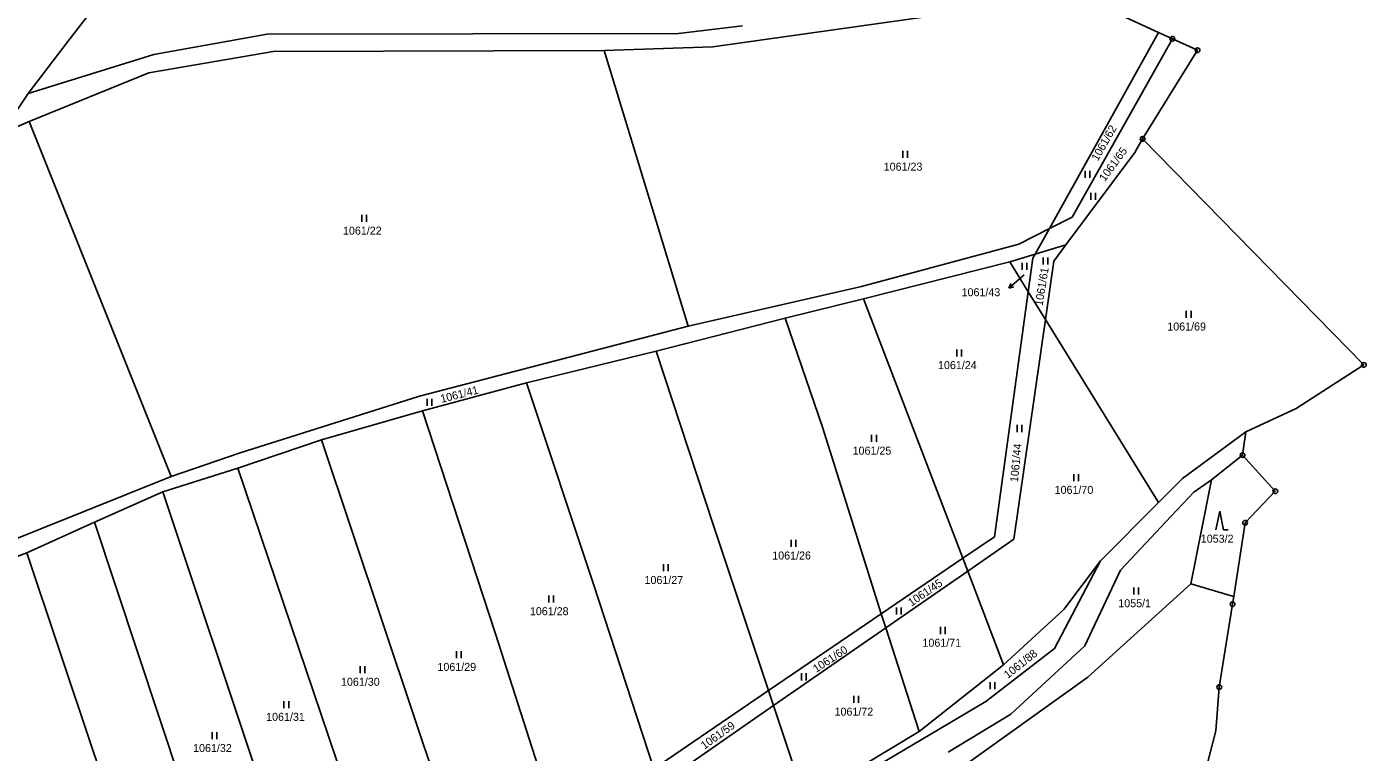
# Model space of a CAD drawing. Extents: x -794142 to -791199, y -1109267 to -1105626.
# Drawn here: x -791483.8 to -791199.2, y -1108972 to -1108817.8 of the extents above; entities that cross this region are included whole.
import ezdxf

# ---------------------------------------------------------------- set-up
doc = ezdxf.new("R2010")
doc.units = 0
for name, color, linetype in [('Komunikace', 7, 'Continuous'), ('Vrstva 1', 7, 'Continuous'), ('Vrstva 14', 7, 'Continuous'), ('Vrstva 16', 7, 'Continuous'), ('Vrstva 23', 7, 'Continuous'), ('Vrstva 28', 7, 'Continuous'), ('Vrstva 4', 7, 'Continuous')]:
    doc.layers.add(name, color=color, linetype=linetype)

msp = doc.modelspace()

# ---------------------------------------------------------------- linework, layer by layer
at = {"layer": 'Komunikace'}
msp.add_line((-791271.91, -1108870.51), (-791272.89, -1108871.38), dxfattribs=at)
at = {"layer": 'Vrstva 1'}
for p, q in [((-791475.05, -1108820.89), (-791464.89, -1108807.59)), ((-791292.25, -1108815.59), (-791338.01, -1108822.07)), ((-791432.75, -1108819.34), (-791456.84, -1108823.68)), ((-791345.32, -1108819.21), (-791432.75, -1108819.34)), ((-791331.75, -1108817.59), (-791345.32, -1108819.21)), ((-791266.51, -1108860.69), (-791243.32, -1108818.98)), ((-791483.53, -1108831.99), (-791475.05, -1108820.89)), ((-791338.01, -1108822.07), (-791361.11, -1108822.84)), ((-791261.7, -1108858.25), (-791240.37, -1108820.33)), ((-791456.84, -1108823.68), (-791483.53, -1108831.99)), ((-791431.44, -1108823.06), (-791457.9, -1108827.57)), ((-791361.11, -1108822.84), (-791431.44, -1108823.06)), ((-791343.3, -1108881.43), (-791361.11, -1108822.84)), ((-791457.9, -1108827.57), (-791483.28, -1108837.93)), ((-791487.36, -1108837.71), (-791483.53, -1108831.99)), ((-791490.23, -1108840.92), (-791483.28, -1108837.93)), ((-791453.12, -1108913.4), (-791483.28, -1108837.93)), ((-791248.37, -1108844.49), (-791246.73, -1108841.63)), ((-791263, -1108864.16), (-791248.37, -1108844.49)), ((-791266.51, -1108860.69), (-791261.7, -1108858.25)), ((-791273.05, -1108864), (-791266.51, -1108860.69)), ((-791269.55, -1108866.15), (-791266.51, -1108860.69)), ((-791306.47, -1108872.99), (-791273.05, -1108864)), ((-791269.55, -1108866.15), (-791263, -1108864.16)), ((-791265.55, -1108867.59), (-791263, -1108864.16)), ((-791306, -1108875.6), (-791274.91, -1108867.77)), ((-791274.91, -1108867.77), (-791269.55, -1108866.15)), ((-791271, -1108874.11), (-791274.91, -1108867.77)), ((-791270.01, -1108866.97), (-791271, -1108874.11)), ((-791269.55, -1108866.15), (-791270.01, -1108866.97)), ((-791267.34, -1108880.03), (-791265.55, -1108867.59)), ((-791343.3, -1108881.43), (-791306.47, -1108872.99)), ((-791322.64, -1108879.75), (-791306, -1108875.6)), ((-791284.92, -1108930.76), (-791306, -1108875.6)), ((-791278.2, -1108926.18), (-791271, -1108874.11)), ((-791267.34, -1108880.03), (-791271, -1108874.11)), ((-791400.36, -1108896.29), (-791343.3, -1108881.43)), ((-791350.08, -1108886.76), (-791322.64, -1108879.75)), ((-791314.75, -1108902.86), (-791322.64, -1108879.75)), ((-791274.06, -1108926.68), (-791267.34, -1108880.03)), ((-791243.32, -1108918.94), (-791267.34, -1108880.03)), ((-791377.61, -1108893.46), (-791350.08, -1108886.76)), ((-791350.08, -1108886.76), (-791337.94, -1108923.6)), ((-791399.71, -1108899.45), (-791377.61, -1108893.46)), ((-791377.61, -1108893.46), (-791363.36, -1108936.25)), ((-791438.71, -1108908.39), (-791400.36, -1108896.29)), ((-791421.16, -1108905.56), (-791399.71, -1108899.45)), ((-791384.24, -1108946.84), (-791399.71, -1108899.45)), ((-791302.27, -1108942.58), (-791314.75, -1108902.86)), ((-791224.77, -1108903.92), (-791238.23, -1108913.83)), ((-791438.95, -1108911.62), (-791421.16, -1108905.56)), ((-791421.16, -1108905.56), (-791401.54, -1108964.23)), ((-791453.12, -1108913.4), (-791438.71, -1108908.39)), ((-791232.05, -1108914.08), (-791225.49, -1108908.84)), ((-791490.67, -1108928.45), (-791453.12, -1108913.4)), ((-791454.92, -1108916.61), (-791438.95, -1108911.62)), ((-791406.1, -1109008.8), (-791438.95, -1108911.62)), ((-791243.32, -1108918.94), (-791238.23, -1108913.83)), ((-791236.44, -1108936.2), (-791232.05, -1108914.08)), ((-791235.81, -1108916.68), (-791232.05, -1108914.08)), ((-791469.39, -1108923.1), (-791454.92, -1108916.61)), ((-791454.92, -1108916.61), (-791426.53, -1109001.71)), ((-791255.65, -1108931.33), (-791243.32, -1108918.94)), ((-791235.81, -1108916.68), (-791240.67, -1108921.84)), ((-791240.67, -1108921.84), (-791251.41, -1108933.26)), ((-791483.78, -1108929.6), (-791469.39, -1108923.1)), ((-791436.19, -1109023.39), (-791469.39, -1108923.1)), ((-791337.94, -1108923.6), (-791326.18, -1108958.88)), ((-791284.92, -1108930.76), (-791278.2, -1108926.18)), ((-791283.88, -1108933.48), (-791274.06, -1108926.68)), ((-791497.78, -1108934.85), (-791483.78, -1108929.6)), ((-791469.89, -1108971.15), (-791483.78, -1108929.6)), ((-791302.27, -1108942.58), (-791284.92, -1108930.76)), ((-791283.88, -1108933.48), (-791284.92, -1108930.76)), ((-791265.43, -1108949.97), (-791255.65, -1108931.33)), ((-791263.49, -1108941.65), (-791255.65, -1108931.33)), ((-791251.41, -1108933.26), (-791257.46, -1108946.04)), ((-791301.3, -1108945.56), (-791283.88, -1108933.48)), ((-791276.26, -1108953.4), (-791283.88, -1108933.48)), ((-791258.33, -1108956.04), (-791236.44, -1108936.2)), ((-791236.44, -1108936.2), (-791227.62, -1108938.8)), ((-791350.58, -1108975.51), (-791363.36, -1108936.25)), ((-791227.62, -1108938.8), (-791227.35, -1108938.88)), ((-791276.26, -1108953.4), (-791263.49, -1108941.65)), ((-791326.18, -1108958.88), (-791302.27, -1108942.58)), ((-791301.3, -1108945.56), (-791302.27, -1108942.58)), ((-791370.82, -1108988.65), (-791384.24, -1108946.84)), ((-791325.12, -1108962.07), (-791301.3, -1108945.56)), ((-791294.17, -1108967.57), (-791301.3, -1108945.56)), ((-791257.46, -1108946.04), (-791259.03, -1108949.35)), ((-791280, -1108961.18), (-791265.43, -1108949.97)), ((-791259.03, -1108949.35), (-791274.69, -1108963.9)), ((-791276.26, -1108953.4), (-791294.17, -1108967.57)), ((-791258.33, -1108956.04), (-791286.05, -1108975.86)), ((-791350.58, -1108975.51), (-791326.18, -1108958.88)), ((-791326.18, -1108958.88), (-791325.12, -1108962.07)), ((-791280, -1108961.18), (-791317.94, -1108983.62)), ((-791389.76, -1108999.49), (-791401.54, -1108964.23)), ((-791349.46, -1108978.94), (-791325.12, -1108962.07)), ((-791325.12, -1108962.07), (-791318.37, -1108982.33)), ((-791288.06, -1108972.01), (-791274.69, -1108963.9)), ((-791294.17, -1108967.57), (-791316.56, -1108981)), ((-791450.19, -1109029.44), (-791469.89, -1108971.15))]:
    msp.add_line(p, q, dxfattribs=at)
at = {"layer": 'Vrstva 16'}
for p, q in [((-791272.89, -1108871.38), (-791275.139, -1108873.364)), ((-791275.139, -1108873.364), (-791274.72, -1108872.328)), ((-791275.139, -1108873.364), (-791274.058, -1108873.078))]:
    msp.add_line(p, q, dxfattribs=at)
at = {"layer": 'Vrstva 23'}
for p, q in [((-791297.7, -1108845.67), (-791297.7, -1108844.17)), ((-791296.7, -1108844.17), (-791296.7, -1108845.67)), ((-791258.93, -1108849.89), (-791258.93, -1108848.39)), ((-791257.93, -1108848.39), (-791257.93, -1108849.89)), ((-791257.72, -1108854.56), (-791257.72, -1108853.06)), ((-791256.72, -1108853.06), (-791256.72, -1108854.56)), ((-791412.61, -1108859.27), (-791412.61, -1108857.77)), ((-791411.61, -1108857.77), (-791411.61, -1108859.27)), ((-791267.87, -1108868.3), (-791267.87, -1108866.8)), ((-791266.87, -1108866.8), (-791266.87, -1108868.3)), ((-791272.34, -1108869.46), (-791272.34, -1108867.96)), ((-791271.34, -1108867.96), (-791271.34, -1108869.46)), ((-791237.43, -1108879.65), (-791237.43, -1108878.15)), ((-791236.43, -1108878.15), (-791236.43, -1108879.65)), ((-791286.19, -1108887.86), (-791286.19, -1108886.36)), ((-791285.19, -1108886.36), (-791285.19, -1108887.86)), ((-791398.72, -1108898.36), (-791398.72, -1108896.86)), ((-791397.72, -1108896.86), (-791397.72, -1108898.36)), ((-791304.29, -1108906.04), (-791304.29, -1108904.54)), ((-791303.29, -1108904.54), (-791303.29, -1108906.04)), ((-791273.36, -1108903.93), (-791273.36, -1108902.43)), ((-791272.36, -1108902.43), (-791272.36, -1108903.93)), ((-791261.34, -1108914.37), (-791261.34, -1108912.87)), ((-791260.34, -1108912.87), (-791260.34, -1108914.37)), ((-791231.13, -1108924.75), (-791230.33, -1108920.75)), ((-791230.33, -1108920.75), (-791229.53, -1108924.75)), ((-791229.53, -1108924.75), (-791228.53, -1108924.75)), ((-791321.38, -1108928.33), (-791321.38, -1108926.83)), ((-791320.38, -1108926.83), (-791320.38, -1108928.33)), ((-791348.49, -1108933.53), (-791348.49, -1108932.03)), ((-791347.49, -1108932.03), (-791347.49, -1108933.53)), ((-791372.9, -1108940.16), (-791372.9, -1108938.66)), ((-791371.9, -1108938.66), (-791371.9, -1108940.16)), ((-791248.57, -1108938.47), (-791248.57, -1108936.97)), ((-791247.57, -1108936.97), (-791247.57, -1108938.47)), ((-791298.99, -1108942.71), (-791298.99, -1108941.21)), ((-791297.99, -1108941.21), (-791297.99, -1108942.71)), ((-791289.66, -1108946.87), (-791289.66, -1108945.37)), ((-791288.66, -1108945.37), (-791288.66, -1108946.87)), ((-791392.52, -1108952), (-791392.52, -1108950.5)), ((-791391.52, -1108950.5), (-791391.52, -1108952)), ((-791413, -1108955.17), (-791413, -1108953.67)), ((-791412, -1108953.67), (-791412, -1108955.17)), ((-791319.18, -1108956.72), (-791319.18, -1108955.22)), ((-791318.18, -1108955.22), (-791318.18, -1108956.72)), ((-791279.1, -1108958.58), (-791279.1, -1108957.08)), ((-791278.1, -1108957.08), (-791278.1, -1108958.58)), ((-791429.15, -1108962.62), (-791429.15, -1108961.12)), ((-791428.15, -1108961.12), (-791428.15, -1108962.62)), ((-791308.11, -1108961.52), (-791308.11, -1108960.02)), ((-791307.11, -1108960.02), (-791307.11, -1108961.52)), ((-791444.44, -1108969.25), (-791444.44, -1108967.75)), ((-791443.44, -1108967.75), (-791443.44, -1108969.25))]:
    msp.add_line(p, q, dxfattribs=at)
at = {"layer": 'Vrstva 28'}
for centre, radius in [((-791240.37, -1108820.33), 0.5), ((-791240.37, -1108820.33), 0.01), ((-791235.04, -1108822.78), 0.5), ((-791235.04, -1108822.78), 0.01), ((-791246.73, -1108841.63), 0.5), ((-791246.73, -1108841.63), 0.01), ((-791199.71, -1108889.67), 0.5), ((-791199.71, -1108889.67), 0.01), ((-791225.49, -1108908.84), 0.5), ((-791225.49, -1108908.84), 0.01), ((-791218.52, -1108916.5), 0.5), ((-791218.52, -1108916.5), 0.01), ((-791224.93, -1108923.21), 0.5), ((-791224.93, -1108923.21), 0.01), ((-791227.61, -1108940.53), 0.5), ((-791227.61, -1108940.53), 0.01), ((-791230.42, -1108958.14), 0.5), ((-791230.42, -1108958.14), 0.01)]:
    msp.add_circle(centre, radius, dxfattribs=at)
at = {"layer": 'Vrstva 4'}
for p, q in [((-791260.86, -1108810.93), (-791243.32, -1108818.98)), ((-791243.32, -1108818.98), (-791240.37, -1108820.33)), ((-791240.37, -1108820.33), (-791235.04, -1108822.78)), ((-791246.73, -1108841.63), (-791235.04, -1108822.78)), ((-791199.71, -1108889.67), (-791246.73, -1108841.63)), ((-791214.09, -1108898.9), (-791199.71, -1108889.67)), ((-791214.09, -1108898.9), (-791224.77, -1108903.92)), ((-791224.77, -1108903.92), (-791225.49, -1108908.84)), ((-791225.49, -1108908.84), (-791218.52, -1108916.5)), ((-791224.93, -1108923.21), (-791218.52, -1108916.5)), ((-791227.35, -1108938.88), (-791224.93, -1108923.21)), ((-791227.61, -1108940.53), (-791227.35, -1108938.88)), ((-791230.42, -1108958.14), (-791227.61, -1108940.53)), ((-791231.13, -1108967.48), (-791230.42, -1108958.14)), ((-791231.13, -1108967.48), (-791240.3, -1109002.82))]:
    msp.add_line(p, q, dxfattribs=at)

# ---------------------------------------------------------------- texts
at = {"layer": 'Vrstva 14'}
for s, rotation, p in [('1061/62', 60.22512, (-791256.237, -1108846.458)), ('1061/65', 53.64828, (-791254.734, -1108850.804)), ('1061/61', 80.78535, (-791267.968, -1108877.203)), ('1061/41', 14.17581, (-791395.674, -1108897.746)), ('1061/44', 84.49074, (-791273.201, -1108914.646)), ('1061/45', 34.33968, (-791295.837, -1108941.059)), ('1061/60', 33.31935, (-791316.069, -1108955.151)), ('1061/88', 38.3958, (-791275.361, -1108956.428)), ('1061/59', 35.52372, (-791339.833, -1108971.47))]:
    msp.add_text(s, height=1.7, rotation=rotation, dxfattribs=at).set_placement(p)
for s, height, p in [('1061/23', 1.7, (-791301.725, -1108848.37)), ('1061/22', 1.7, (-791416.615, -1108861.97)), ('1061/43', 0.1, (-791272.175, -1108870.51)), ('1061/69', 1.7, (-791241.476, -1108882.35)), ('1061/24', 1.7, (-791290.191, -1108890.56)), ('1061/25', 1.7, (-791308.332, -1108908.74)), ('1061/70', 1.7, (-791265.411, -1108917.07)), ('1053/2', 1.7, (-791234.358, -1108927.45)), ('1061/26', 1.7, (-791325.405, -1108931.03)), ('1061/27', 1.7, (-791352.552, -1108936.23)), ('1061/28', 1.7, (-791376.905, -1108942.86)), ('1055/1', 1.7, (-791251.888, -1108941.17)), ('1061/71', 1.7, (-791293.495, -1108949.57)), ('1061/29', 1.7, (-791396.545, -1108954.7)), ('1061/30', 1.7, (-791417.035, -1108957.87)), ('1061/31', 1.7, (-791432.949, -1108965.32)), ('1061/72', 1.7, (-791312.172, -1108964.22)), ('1061/32', 1.7, (-791448.465, -1108971.95))]:
    msp.add_text(s, height=height, dxfattribs=at).set_placement(p)
at = {"layer": 'Vrstva 16'}
msp.add_text('1061/43', height=1.7, dxfattribs=at).set_placement((-791285.183, -1108875.06))

doc.saveas('drawing.dxf')
